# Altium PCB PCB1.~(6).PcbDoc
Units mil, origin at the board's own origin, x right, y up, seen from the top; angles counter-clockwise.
Board outline 1610.59 x 1610.59 mil, 2 copper layers (Top Layer, Bottom Layer); 25 components, 8 nets, 53 pads, 6 vias.
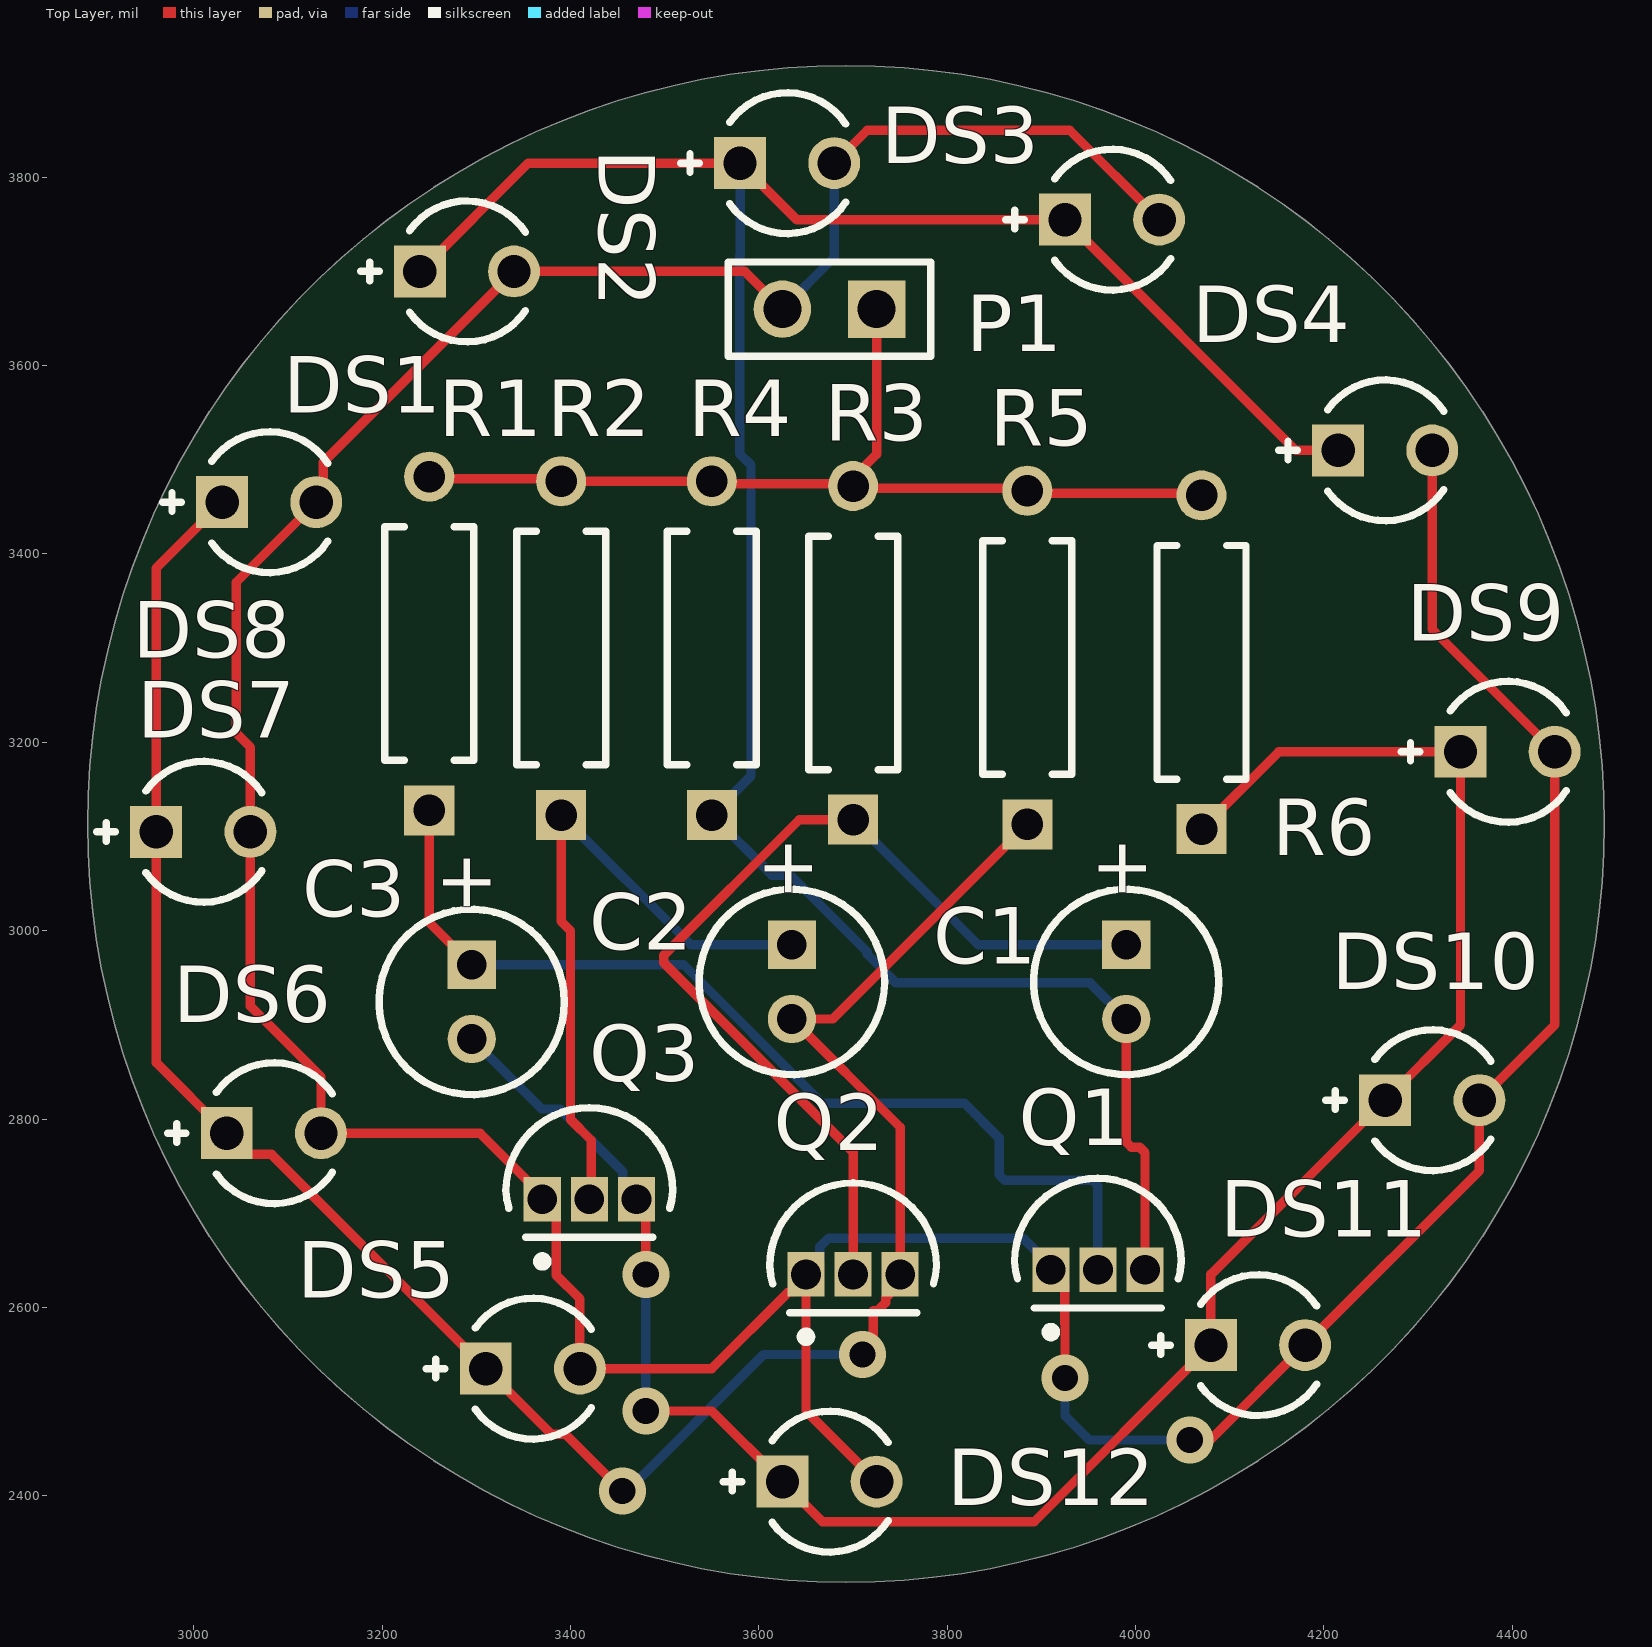
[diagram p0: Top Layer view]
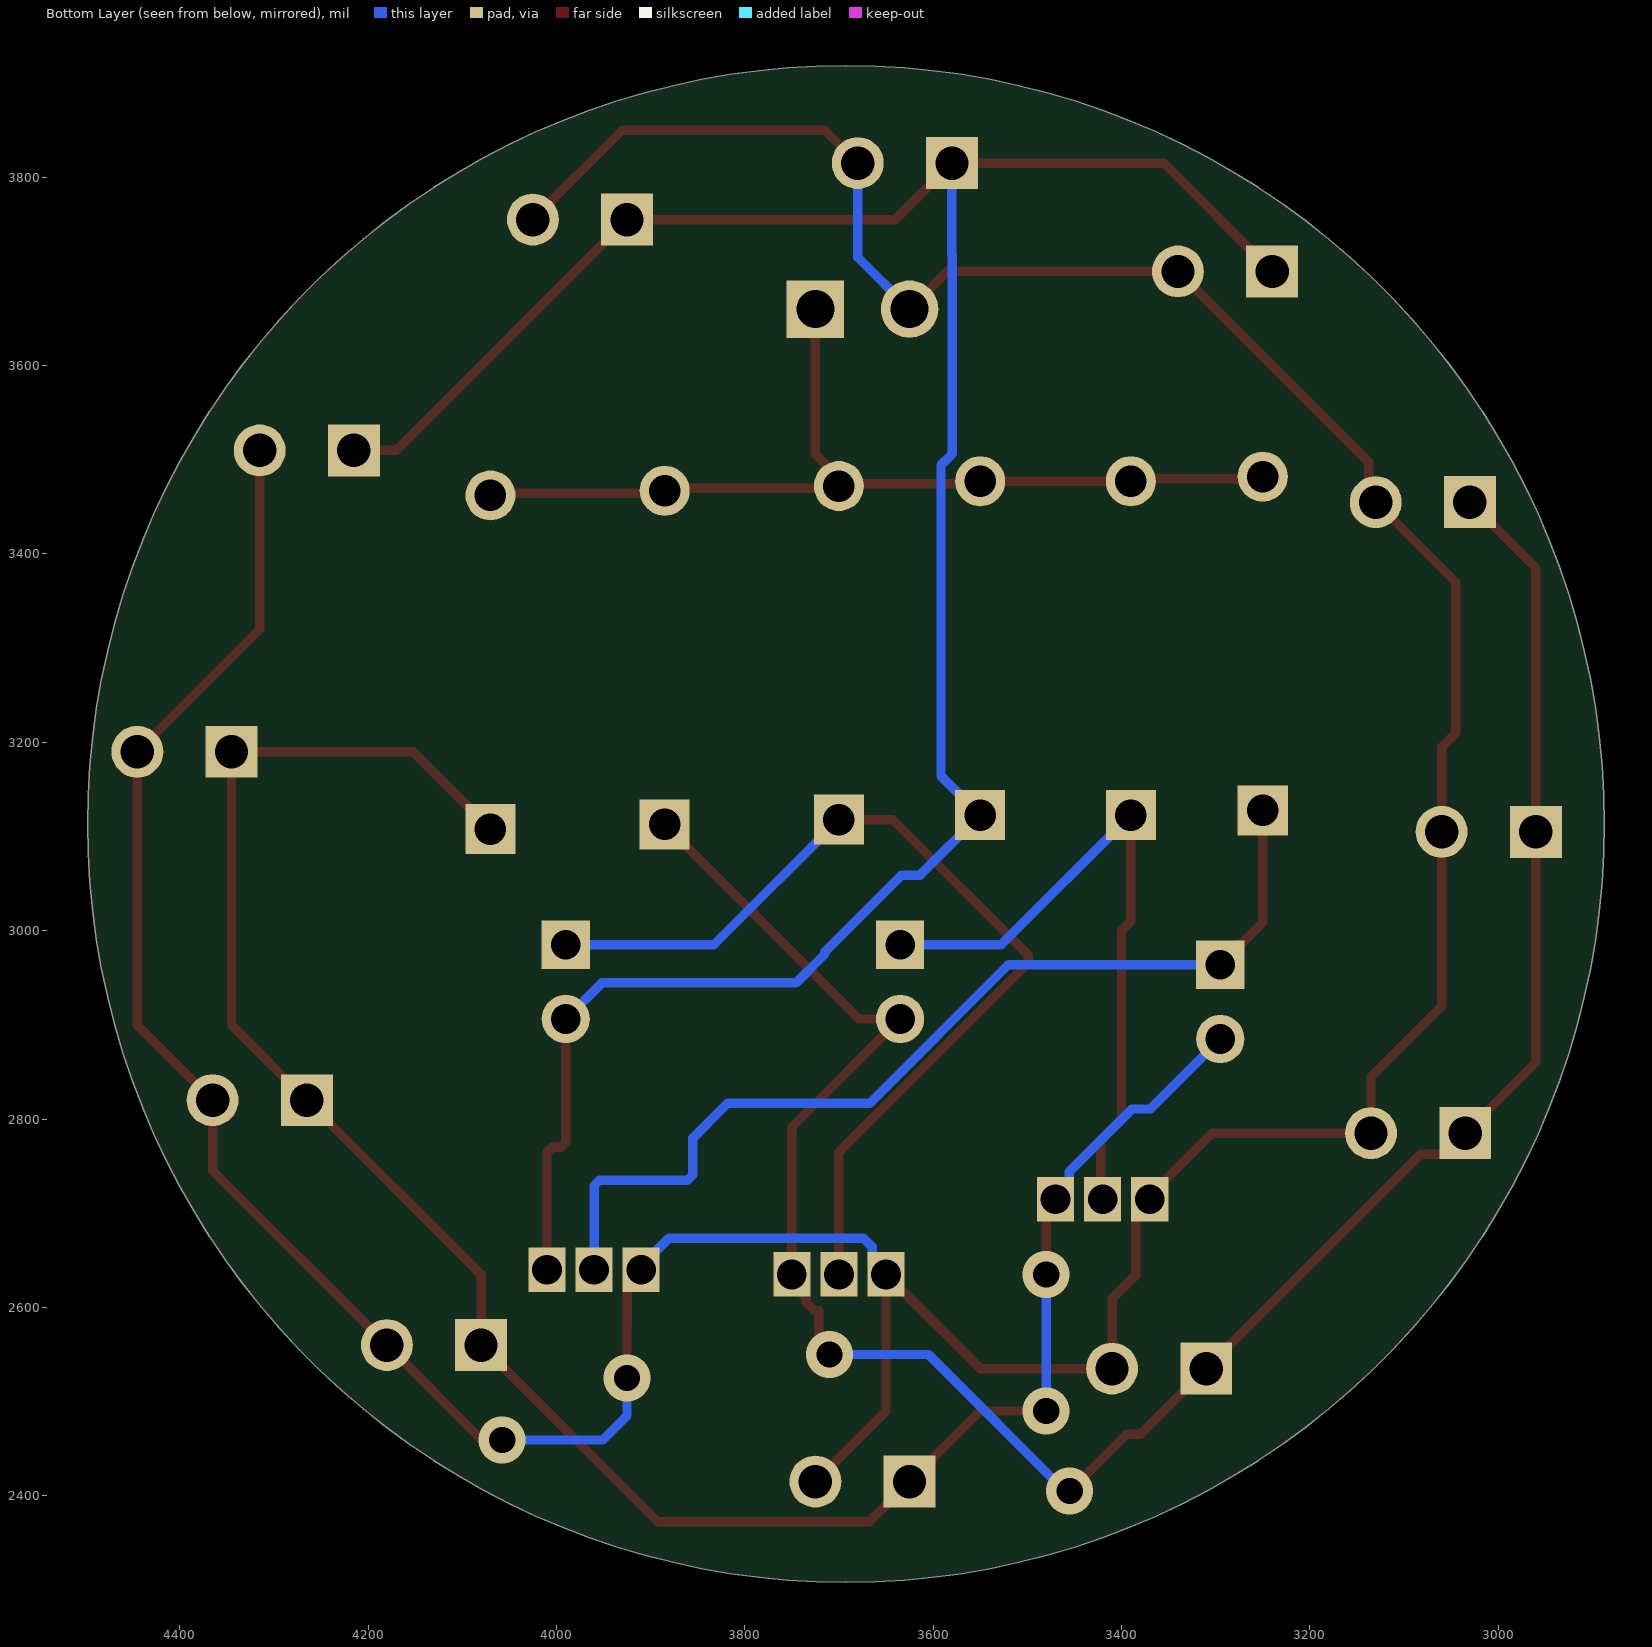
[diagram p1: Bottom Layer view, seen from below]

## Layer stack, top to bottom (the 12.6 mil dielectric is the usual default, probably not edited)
Top Solder: solder mask 0.4, Solder Resist, Dk 3.5
Top Layer: signal copper 1.4
Dielectric 1: dielectric 12.6, FR-4, Dk 4.8
Bottom Layer: signal copper 1.4
Bottom Solder: solder mask 0.4, Solder Resist, Dk 3.5

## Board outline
2887.19,3113.29 ccw(c3692.49,3113.29) 3692.49,2307.99 ccw(c3692.49,3113.29) 4497.78,3113.29 ccw(c3692.49,3113.29) 3692.49,3918.58 ccw(c3692.49,3113.29)

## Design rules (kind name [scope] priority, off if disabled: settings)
Clearance [All] p1: gap=10 ignorepadtopadclearanceinfootprint=FALSE
PolygonConnect [All] p1: connectstyle=Relief reliefconductorwidth=10 reliefentries=4 polygonreliefangle="90 Angle" airgapwidth=10
RoutingVias [All] p1: holewidth=28 width=50 viastyle="Through Hole" minholewidth=28 minwidth=50 maxholewidth=28 maxwidth=50
SolderMaskExpansion [All] p1: expansion=4 istentingtop=FALSE
Width [All] p1: maxlimit=10 minlimit=10 preferedwidth=10
30 further rules are at their usual default settings.

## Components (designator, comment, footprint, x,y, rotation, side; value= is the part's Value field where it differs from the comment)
C1 "ECA1HM220" CAPPR55-200-1100X500X1200 3990,2945.63 r270 top value=22µF
C2 "ECA1HM220" CAPPR55-200-1100X500X1200 3635,2945.63 r270 top value=22µF
C3 "ECA1HM220" CAPPR55-200-1100X500X1200 3295,2924.37 r270 top value=22µF
DS1 "LTL-1CHE" INDPR60-254-520X380X650 3290,3700 r0 top
DS2 "LTL-1CHE" INDPR60-254-520X380X650 3630,3815 r0 top
DS3 "LTL-1CHE" INDPR60-254-520X380X650 3975,3755 r0 top
DS4 "LTL-1CHE" INDPR60-254-520X380X650 4265,3510 r0 top
DS5 "LTL-1CHE" INDPR60-254-520X380X650 3360,2535 r0 top
DS6 "LTL-1CHE" INDPR60-254-520X380X650 3085,2785 r0 top
DS7 "LTL-1CHE" INDPR60-254-520X380X650 3010,3105 r0 top
DS8 "LTL-1CHE" INDPR60-254-520X380X650 3080,3455 r0 top
DS9 "LTL-1CHE" INDPR60-254-520X380X650 4395,3190 r0 top
DS10 "LTL-1CHE" INDPR60-254-520X380X650 4315,2820 r0 top
DS11 "LTL-1CHE" INDPR60-254-520X380X650 4130,2560 r0 top
DS12 "LTL-1CHE" INDPR60-254-520X380X650 3675,2415 r0 top
P1 "TSW-102-26-F-S" SMTC-TSW-102-26-XX-S 3725,3660 r180 top
Q1 "S9013" JSCJ-TO-92-3_V 3960,2640 r0 top
Q2 "S9013" JSCJ-TO-92-3_V 3700,2635 r0 top
Q3 "S9013" JSCJ-TO-92-3_V 3420,2715 r0 top
R1 "MFR-25FBF52-10K" RESA60-630X240 3250,3305 r90 top value=10k
R2 "MFR-25FBF52-10K" RESA60-630X240 3390,3300 r90 top value=10k
R3 "MFR-25FBF52-10K" RESA60-630X240 3700,3295 r90 top value=10k
R4 "MFR-25FBF52-10K" RESA60-630X240 3550,3300 r90 top value=330R
R5 "" RESA60-630X240 3885,3290 r90 top value=330R
R6 "330R" RESA60-630X240 4070,3285 r90 top

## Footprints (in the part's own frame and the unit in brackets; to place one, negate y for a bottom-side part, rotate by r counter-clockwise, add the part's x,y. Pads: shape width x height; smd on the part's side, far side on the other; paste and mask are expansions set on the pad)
CAPPR55-200-1100X500X1200 [mm] "THD, 2-Leads, Dia 5mm, Pin Spacing 2mm"
  rect 1.3x1.3 hole 0.8: 1(-1,0)
  round 1.3 hole 0.8: 2(1,0)
  silkscreen extent -2.5,-2.5 2.5,2.5, body extent -2.5,-2.5 2.45,2.5, height 12
INDPR60-254-520X380X650 [mm] "THD, 2-Leads, Dia 3.8mm, Pitch 2.54mm"
  rect 1.4x1.4 hole 0.9: 1(-1.27,0)
  round 1.4 hole 0.9: 2(1.27,0)
  silkscreen extent -2.87,-1.9 1.58,1.9, body extent -1.9,-1.9 1.9,1.9, height 6.5
JSCJ-TO-92-3_V [mm] "TO-92, 3-leads, Height 4.7mm, Pitch 1.27mm"
  rect 1x1.2 hole 0.8: 1(-1.27,0) 2(0,0) 3(1.27,0)
  silkscreen extent -2.25,-1.81 2.25,2.47, body extent -2.25,-1.03 2.25,2.47, height 4.7
RESA60-630X240 [mm] "Axial Resistor, 2-Leads, Dia 2.4mm, Body Length 6.3mm"
  rect 1.35x1.35 hole 0.85: 1(-4.5,0)
  round 1.35 hole 0.85: 2(4.5,0)
  silkscreen extent -3.15,-1.2 3.15,1.2, body extent -4.77,-1.19 4.77,1.2, height 2.4
SMTC-TSW-102-26-XX-S [mm] ".025 SQ Post Terminal Strip Assembly, 1x2 Pins, Vertical, 2.54mm Pitch, Male"
  rect 1.55x1.55 hole 1.02: 1(0,0)
  round 1.55 hole 1.02: 2(2.54,0)
  silkscreen extent -1.46,-1.27 4,1.27, body extent -1.4,-1.27 3.81,1.27, height 8.38

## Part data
C1 C2 C3: library part CMP-001-00027-7, "Aluminum Electrolytic Capacitor, 22 uF, +/- 20%, 50 V, -40 to 85 degC, 2-Pin THD, RoHS, Bulk", Capacitor Type=Electrolytic, Case/Package=Radial, Manufacturer=Panasonic, Max Operating Temperature=85°C, Min Operating Temperature=-40°C, Package Description="2-Pin Radial Lead, Dia 5 mm, Height 12 mm", Package Quantity=200, Package Reference=CAPPR55-200-1100X500X1200, Ripple Current=100mA, Tolerance=20%, Voltage Rating=50V
DS1 DS2 DS3 DS4 DS5 DS6 DS7 DS8 DS9 DS10 DS11 DS12: library part CMP-007-00018-2, "LED Uni-Color Red, 100 mW, 30 mA, -55 to 100 degC, 2-Pin THD, RoHS, Bulk", Case/Package=Radial, Colour=Red, Forward Current=20mA, Forward Voltage=2V, Manufacturer=Lite-On, Max Operating Temperature=100°C, Min Operating Temperature=-55°C, Package Description="2-Pin Through Hole Device, Dia 3.8 mm, Pitch 2.54 mm", Package Quantity=1000
P1: library part CMP-1024-00329-1, "0.025\" SQ Post Header, Through-hole, Vertical, -55 to 125 degC, 2.54 mm Pitch, 2-Pin, Male, RoHS", Manufacturer=Samtec, Temperature Range="-55 to 125 degC"
Q1 Q2 Q3: library part CMP-013-00000-3, "Transistor, NPN, 0.1 uA, 150 MHz, 3-Pin TO-92", Case/Package=TO-92-3, Manufacturer="Jiangsu Changjiang Electronics Technology", Package Description="3-Pin Through Hole Device, Height 4.7 mm, Pitch 2.3 mm"
R1 R2 R3 R4 R5 R6: library part CMP-009-00047-4, "Axial Resistor, 10 KOhm, +/- 1%, 0.25 W, -55 to 155 degC, 2-Pin THD, RoHS, Bulk", Case/Package=Axial, Manufacturer=Yageo, Max Operating Temperature=155°C, Min Operating Temperature=-55°C, Package Description="2-Pin Axial Lead, Dia 2.4 mm, Body Length 6.3 mm", Package Quantity=200, Package Reference=MFR-25, Power=250mW, Tolerance=1%, Voltage Rating=250V

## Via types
v1: diameter 50, hole 28, Top Layer to Bottom Layer, 6 vias

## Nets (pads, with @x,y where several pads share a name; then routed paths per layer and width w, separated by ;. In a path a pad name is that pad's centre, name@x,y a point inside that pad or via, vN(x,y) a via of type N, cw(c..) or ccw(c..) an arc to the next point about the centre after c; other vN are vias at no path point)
NetC1_1: C1.1 Q2.2 R3.1 | length 1027.7
  Top Layer w10: Q2.2 3700,2765 3499.14,2965.86 3499.14,2974.14 3642.83,3117.83 R3.1
  Bottom Layer w10: R3.1 3832.83,2985 C1.1
NetC1_2: C1.2 DS1.1 DS2.1 DS3.1 DS4.1 Q1.3 R4.1 | length 2674.4
  Top Layer w10: DS1.1 3355,3815 DS2.1 3640,3755 DS3.1 4170,3510 DS4.1 ; C1.2 3990,2775.59 3995.31,2770.27 4004.14,2770.27 4010,2764.41 Q1.3
  Bottom Layer w10: DS2.1 3580,3717.05 3579.49,3716.54 3579.49,3506.47 3591.57,3494.39 3591.57,3164.41 R4.1 3613.8,3059.03 3633.36,3059.03 3715,2977.39 3715,2975 3745.43,2944.57 3951.69,2944.57 C1.2
NetC2_1: C2.1 Q3.2 R2.1 | length 724.1
  Top Layer w10: R2.1 3390,3010 3400,3000 3400,2799.52 3422.09,2777.43 3422.09,2717.09 Q3.2
  Bottom Layer w10: R2.1 3527.83,2985 C2.1
NetC2_2: C2.2 DS5.1 DS6.1 DS7.1 DS8.1 Q2.3 R5.1 | length 2402
  Top Layer w10: DS8.1 2960,3385 DS7.1 2960,2860 DS6.1 3057.56,2762.44 3082.56,2762.44 DS5.1 ; DS5.1@3308.86,2527.37 3317.63,2527.37 3379.75,2465.25 3394.75,2465.25 v1(3455,2405) ; v1(3710,2550) 3721.38,2561.38 3721.38,2596.38 3725.9,2596.38 3734.69,2605.16 3734.69,2609.69 3750,2625 Q2.3 3750,2791.26 C2.2 3678.43,2906.26 R5.1
  Bottom Layer w10: v1(3455,2405) 3445,2405 3448.36,2401.64 3456.64,2401.64 3605,2550 v1(3710,2550)
NetC3_1: C3.1 Q1.2 R1.1 | length 1057
  Top Layer w10: R1.1 3250,3008.74 C3.1
  Bottom Layer w10: C3.1 3520.12,2963.74 3667.07,2816.79 3818.21,2816.79 3855,2780 3855,2740.86 3860.86,2735 3954.14,2735 3960,2729.14 Q1.2
NetC3_2: C3.2 DS9.1 DS10.1 DS11.1 DS12.1 Q3.3 R6.1 | length 2258.2
  Top Layer w10: Q3.3 3480,2705 v1(3480,2635) ; v1(3480,2490) 3550,2490 DS12.1 3667.56,2372.44 3892.44,2372.44 DS11.1 4080,2635 DS10.1 4345,2900 DS9.1 4152.17,3190 R6.1
  Bottom Layer w10: C3.2 3369.34,2810.66 3388.86,2810.66 3455.31,2744.21 3455.31,2729.69 Q3.3 ; v1(3480,2490) v1(3480,2635)
NetDS1_2: DS1.2 DS2.2 DS3.2 DS4.2 DS5.2 DS6.2 DS7.2 DS8.2 DS9.2 DS10.2 DS11.2 DS12.2 P1.2 Q1.1 Q2.1 Q3.1 | length 4833.3
  Top Layer w10: P1.2 3585,3700 DS1.2 3137.56,3497.56 3137.56,3462.56 DS8.2 3045,3370 3045,3210 3060,3195 DS7.2 3060,2920 3135,2845 DS6.2 3303.94,2785 3370,2718.94 Q3.1 3384.69,2700.31 3384.69,2634.45 3410,2609.14 DS5.2 3550,2535 3631.38,2616.38 3635.31,2616.38 3650,2631.06 Q2.1 3650,2490 DS12.2 ; DS2.2 3715,3850 3930,3850 DS3.2 ; Q1.1 3924.69,2625.31 3924.69,2582.59 3925,2582.27 v1(3925,2525) ; v1(4057.58,2459.22) 4079.22,2459.22 DS11.2 4365,2745 DS10.2 4445,2900 DS9.2 4315,3320 DS4.2
  Bottom Layer w10: P1.2 3680,3715 DS2.2 ; Q2.1 3664.69,2649.69 3664.69,2664.21 3674.1,2673.62 3880.31,2673.62 3910,2643.94 Q1.1 ; v1(3925,2525) 3925,2485 3950.78,2459.22 v1(4057.58,2459.22)
NetP1_1: P1.1 R1.2 R2.2 R3.2 R4.2 R5.2 R6.2 | length 1026.5
  Top Layer w10: R1.2 3252.5,3479.67 3387.5,3479.67 R2.2 R4.2 3552.5,3474.67 3697.5,3474.67 R3.2 ; P1.1 3725,3505.96 3700,3480.96 R3.2 ; R6.2 4067.5,3464.67 3887.5,3464.67 R5.2 3882.5,3469.67 3702.5,3469.67 R3.2

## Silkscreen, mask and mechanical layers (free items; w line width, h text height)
Mechanical 1:
  circle w10: c3692.49,3113.29 r805.29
